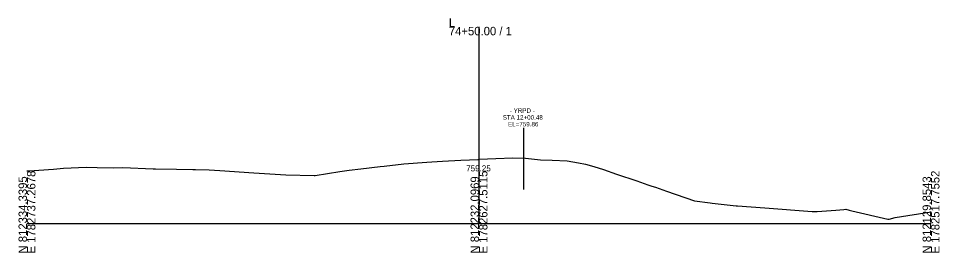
# Model space of a CAD drawing. Extents: x -26 to 7903, y -10 to 9573.
# Drawn here: x 3997.2 to 4302.8, y 5490.3 to 5568 of the extents above; entities that cross this region are included whole.
import ezdxf

# ---------------------------------------------------------------- set-up
doc = ezdxf.new("R2010")
doc.units = 0
for name, color, linetype in [('Exist Cross Section Cell', 7, 'Continuous'), ('Exist XS Center Line Elevation Label', 7, 'Continuous'), ('Exist XS Ground Line', 7, 'Continuous'), ('Prop XS Vertical Lines Alignments', 7, 'Continuous')]:
    doc.layers.add(name, color=color, linetype=linetype)

msp = doc.modelspace()

# ---------------------------------------------------------------- linework, layer by layer
at = {"layer": 'Exist Cross Section Cell'}
for p, q in [((4150, 5500), (4150, 5565.19)), ((4000, 5500), (4150, 5500)), ((4150, 5500), (4300, 5500))]:
    msp.add_line(p, q, dxfattribs=at)
at = {"layer": 'Exist XS Ground Line'}
for p, q in [((4134.37, 5520.42), (4137.87, 5520.62)), ((4137.87, 5520.62), (4144, 5520.94)), ((4144, 5520.94), (4149.67, 5521.24)), ((4149.67, 5521.24), (4150, 5521.25)), ((4150, 5521.25), (4155.61, 5521.49)), ((4155.61, 5521.49), (4161.22, 5521.73)), ((4161.22, 5521.73), (4165.44, 5521.65)), ((4165.44, 5521.65), (4170.4, 5521.09)), ((4170.4, 5521.09), (4174.27, 5520.96)), ((4174.27, 5520.96), (4179.29, 5520.73)), ((4179.29, 5520.73), (4183.03, 5520.03)), ((4000.67, 5517.46), (4008.83, 5518.01)), ((4008.83, 5518.01), (4012.11, 5518.33)), ((4012.11, 5518.33), (4019.59, 5518.61)), ((4019.59, 5518.61), (4023.34, 5518.53)), ((4023.34, 5518.53), (4028.78, 5518.44)), ((4028.78, 5518.44), (4031.84, 5518.51)), ((4031.84, 5518.51), (4041.83, 5518.14)), ((4041.83, 5518.14), (4042.69, 5518.07)), ((4042.69, 5518.07), (4049.59, 5517.98)), ((4049.59, 5517.98), (4055.01, 5517.89)), ((4055.01, 5517.89), (4055.46, 5517.85)), ((4055.46, 5517.85), (4055.92, 5517.84)), ((4055.92, 5517.84), (4060.49, 5517.74)), ((4060.49, 5517.74), (4063.98, 5517.58)), ((4063.98, 5517.58), (4075.32, 5516.73)), ((4103.85, 5517.25), (4106.9, 5517.61)), ((4106.9, 5517.61), (4110.8, 5518.05)), ((4110.8, 5518.05), (4117.22, 5518.87)), ((4117.22, 5518.87), (4118.52, 5519.02)), ((4118.52, 5519.02), (4125.11, 5519.72)), ((4125.11, 5519.72), (4132.68, 5520.3)), ((4132.68, 5520.3), (4134.37, 5520.42)), ((4183.03, 5520.03), (4185.33, 5519.61)), ((4185.33, 5519.61), (4188.16, 5518.83)), ((4188.16, 5518.83), (4191.32, 5517.86)), ((4191.32, 5517.86), (4195.65, 5516.33)), ((4000, 5517.42), (4000.67, 5517.46)), ((4075.32, 5516.73), (4085.87, 5516.08)), ((4085.87, 5516.08), (4095.26, 5515.88)), ((4095.26, 5515.88), (4095.58, 5515.89)), ((4095.58, 5515.89), (4103.85, 5517.25)), ((4195.65, 5516.33), (4202.42, 5514.06)), ((4202.42, 5514.06), (4205.98, 5512.8)), ((4205.98, 5512.8), (4207.35, 5512.34)), ((4207.35, 5512.34), (4208.55, 5512.05)), ((4208.55, 5512.05), (4212.25, 5510.63)), ((4212.25, 5510.63), (4221.52, 5507.43)), ((4221.52, 5507.43), (4226.76, 5506.79)), ((4226.76, 5506.79), (4227.33, 5506.73)), ((4227.33, 5506.73), (4235.33, 5505.85)), ((4235.33, 5505.85), (4235.82, 5505.81)), ((4235.82, 5505.81), (4244.9, 5505.2)), ((4244.9, 5505.2), (4260.56, 5503.97)), ((4260.56, 5503.97), (4261.37, 5503.91)), ((4261.37, 5503.91), (4261.86, 5503.95)), ((4261.86, 5503.95), (4262.25, 5503.98)), ((4262.25, 5503.98), (4268.41, 5504.37)), ((4268.41, 5504.37), (4271.12, 5504.65)), ((4271.12, 5504.65), (4271.69, 5504.67)), ((4271.69, 5504.67), (4272.8, 5504.41)), ((4272.8, 5504.41), (4273.72, 5504.19)), ((4273.72, 5504.19), (4285.63, 5501.35)), ((4288.05, 5501.96), (4300, 5503.8)), ((4285.63, 5501.35), (4286.07, 5501.36)), ((4286.07, 5501.36), (4288.05, 5501.96))]:
    msp.add_line(p, q, dxfattribs=at)
at = {"layer": 'Prop XS Vertical Lines Alignments'}
msp.add_line((4164.81, 5531.66), (4164.81, 5511.25), dxfattribs=at)

# ---------------------------------------------------------------- texts
at = {"layer": 'Exist Cross Section Cell'}
for s, p in [('L', (4140, 5565.19)), ('74+50.00 / 1', (4140, 5562.39))]:
    msp.add_text(s, height=2.8, dxfattribs=at).set_placement(p)
for s, p in [('N 812334.3395', (4000, 5490)), ('E 1782737.2678', (4002.8, 5490)), ('N 812232.0969', (4150, 5490)), ('E 1782627.5115', (4152.8, 5490)), ('N 812129.8543', (4300, 5490)), ('E 1782517.7552', (4302.8, 5490))]:
    msp.add_text(s, height=2.8, rotation=90, dxfattribs=at).set_placement(p)
at = {"layer": 'Exist XS Center Line Elevation Label'}
msp.add_text('759.25', height=2, dxfattribs=at).set_placement((4145.74, 5517.25))
at = {"layer": 'Prop XS Vertical Lines Alignments'}
for s, p in [('STA 12+00.48', (4157.87, 5534.41)), ('- YRPD -', (4160.23, 5536.66)), ('EL=759.86', (4159.64, 5532.16))]:
    msp.add_text(s, height=1.5, dxfattribs=at).set_placement(p)

doc.saveas('drawing.dxf')
